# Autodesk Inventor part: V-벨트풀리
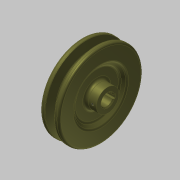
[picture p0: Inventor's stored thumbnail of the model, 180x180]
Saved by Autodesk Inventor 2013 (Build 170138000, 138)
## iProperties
Company: 한국ATC센터
Created: 2015-12
Part Number: V-벨트풀리
Document SubType Name: Modeling
Designer: mdu
Density: 7.25 g/cm^3
Mass: 588.269 g
Surface Area: 211.373 cm^2
Volume: 81.1405 cm^3
Material: 주철
Author: mdu
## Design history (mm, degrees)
sketch "스케치1"
  geometry: L1 (-13, 0)-(13, 0); L2 (-13, 0)-(-13, 11.5); L3 (-13, 11.5)-(-9, 11.5); L4 (-9, 11.5)-(-9, 23); L5 (-9, 23)-(-13, 27); L6 (-13, 27)-(-13, 42.7); L7 (-13, 42.7)-(-8.325, 42.7); L8 (-8.325, 42.7)-(-5.574, 33.7); L9 (-5.574, 33.7)-(-1.426, 33.7); L10 (-1.426, 33.7)-(1.325, 42.7); L11 (1.325, 42.7)-(6, 42.7); L12 (6, 42.7)-(6, 27); L13 (6, 27)-(2, 23); L14 (2, 23)-(2, 11.5); L15 (2, 11.5)-(13, 11.5); L16 (13, 11.5)-(13, 0); L17 (-7.5, 40)-(0.5, 40); 2 further points
  constraints: 34 end point, 6 parallel, 5 collinear, 5 equal length, 4 perpendicular, 2 point on line, 1 coincident, 1 horizontal, 1 midpoint
  dimensions: "d0" = 26 distance of L1.start L1.end; "d1" = 2.7 distance between parallel lines of L7 L17; "d2" = 6.3 distance between parallel lines of L9 L17; "d3" = 8 distance of L17.start L17.end; "d4" = 34 deg angle of L10 L8; "d5" = 19 distance between parallel lines of L12 L6; "d7" = 23 diameter of L15 L1; "d8" = 46 diameter of L13.end L1; "d9" = 54 diameter of L12.end L1; "d10" = 4 distance between parallel lines of L2 L4; "d11" = 80 diameter of L17 L1
revolve "회전1" sketch "스케치1" stored, may be unused: angle "d12" = 90 deg
sketch "스케치2"
  geometry: L1 (-2, 5.657)-(-2, 7.8); L2 (-2, 7.8)-(2, 7.8); L3 (2, 7.8)-(2, 5.657); A1 r 6 centre (0, 0) between (-2, 5.657) and (2, 5.657); 1 further point
  constraints: 6 end point, 2 parallel, 2 point on circle, 1 centre point, 1 coincident, 1 perpendicular, 1 vertical
  dimensions: "d13" = 12 diameter of A1; "d14" = 13.8 dimension on A1 L2; "d15" = 4 distance of L1.end L2.end
extrude "돌출1" cut sketch "스케치2" stored distance "d16" = 10; taper "d17" = 0 deg
node "작업 평면1"
sketch "스케치3"
  geometry: L1 (-5.5, 11.5)-(-5.5, -11.5) reference; L2 (20.5, 27)-(20.5, -27) reference; 3 further points
  constraints: 1 horizontal alignment, 1 midpoint
  dimensions: "d18" = 4 distance from line of point (-1.5, 0) L1; "d33" = 22 distance from line of point (-1.5, 0) L2 (derived)
hole "구멍1" sketch "스케치3" at (-1.5, 0) diameter "d19" = 2.459; stored, may be unused: countersink angle "d23" = 90 deg, drill point angle "d25" = 118 deg; dims "d20" = 6, "d21" = 4, "d22" = 2, "d24" = 8
fillet "모깎기1" dims "d26" = 2, "d27" = 0.5, "d28" = 1, "d29" = 3
chamfer "모따기1" distance "d30" = 1; stored, may be unused: second distance "d31" = 2, angle "d32" = 45 deg
sketch "스케치4" dims "d35" = 70
  geometry: C1 r 3 at (0, 35); 2 further points
  constraints: 2 vertical alignment, 1 centre point, 1 coincident, 2 other
  dimensions: "d34" = 6 diameter of C1
extrude "돌출2" join sketch "스케치4" distance "d36" = 10; taper "d37" = 0 deg
fillet "모깎기2" dims "d38" = 0.5, "d39" = 1
node "솔리드1"
